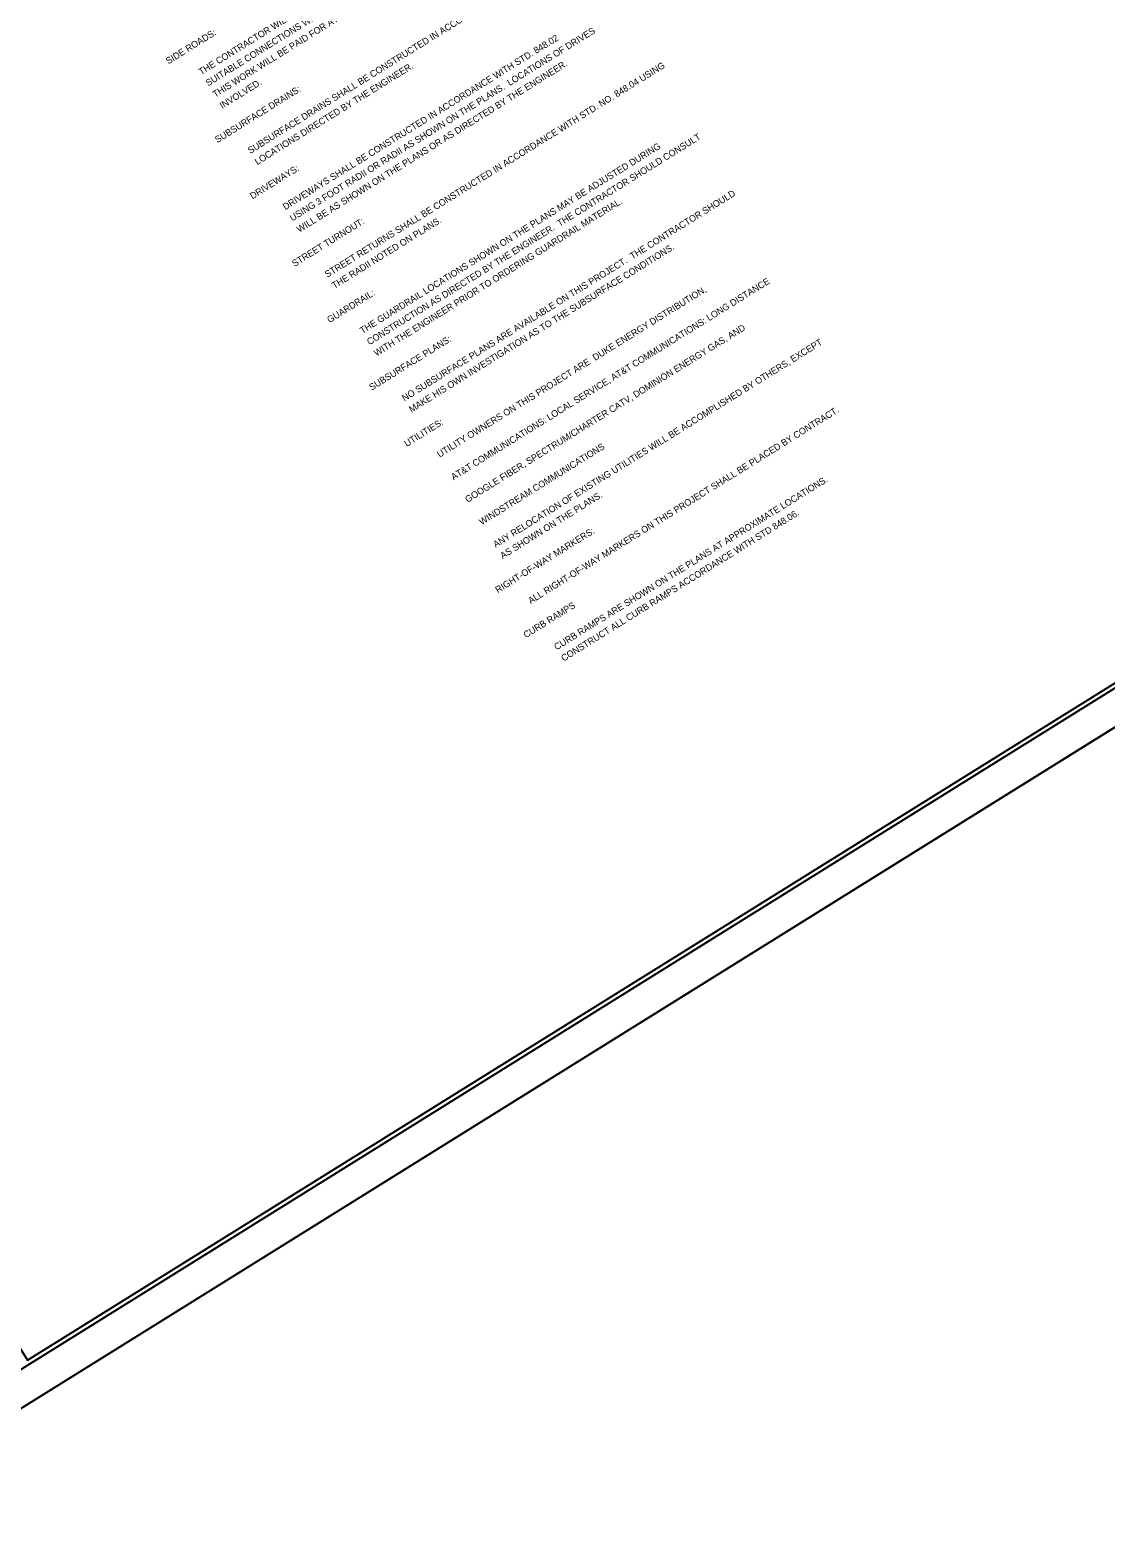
# Model space of a CAD drawing. Extents: x 2047559 to 2049567, y 759970 to 761789.
# Drawn here: x 2048269 to 2048918, y 759970 to 760880 of the extents above; entities that cross this region are included whole.
import ezdxf

# ---------------------------------------------------------------- set-up
doc = ezdxf.new("R2010")
doc.units = 0
for name, color, linetype in [('Sheet Cutting Line CELL', 7, 'Continuous'), ('Sheet Data Text CELL', 7, 'Continuous'), ('Sheet Plan CELL', 7, 'Continuous'), ('Sheet Plot Border Inside CELL', 7, 'Continuous'), ('Sheet Plot Border Outside CELL', 7, 'Continuous')]:
    doc.layers.add(name, color=color, linetype=linetype)

msp = doc.modelspace()

# ---------------------------------------------------------------- linework, layer by layer
at = {"layer": 'Sheet Cutting Line CELL'}
msp.add_line((2048137.94, 759969.81), (2049566.9, 760859.89), dxfattribs=at)
at = {"layer": 'Sheet Plan CELL'}
msp.add_lwpolyline([(2048985.43, 761761.24), (2047712.23, 760968.18), (2048267.37, 760076.94), (2049540.57, 760870)], close=True, dxfattribs=at)
at = {"layer": 'Sheet Plot Border Inside CELL'}
msp.add_lwpolyline([(2048138.4, 759993.66), (2049552.51, 760874.48), (2048994.72, 761769.97), (2047580.61, 760889.15)], close=True, dxfattribs=at)
at = {"layer": 'Sheet Plot Border Outside CELL'}
msp.add_lwpolyline([(2048137.94, 759969.81), (2049566.9, 760859.89), (2048987.97, 761789.33), (2047559, 760899.25)], close=True, dxfattribs=at)

# ---------------------------------------------------------------- texts
at = {"layer": 'Sheet Data Text CELL'}
for s, p in [('         SUITABLE CONNECTIONS WITH ALL ROADS, STREETS, AND DRIVES ENTERING THIS PROJECT.  ', (2048365.04, 760838.51)), ('         THE CONTRACTOR WILL BE REQUIRED TO DO ALL NECESSARY WORK TO PROVIDE ', (2048360.81, 760845.3)), ('         THIS WORK WILL BE PAID FOR AT THE CONTRACT UNIT PRICE FOR THE PARTICULAR ITEMS ', (2048369.27, 760831.72)), ('         SUBSURFACE DRAINS SHALL BE CONSTRUCTED IN ACCORDANCE WITH STD. NO. 815.02 AT ', (2048390.42, 760797.77)), ('SIDE ROADS:  ', (2048352.35, 760858.88)), ('         DRIVEWAYS SHALL BE CONSTRUCTED IN ACCORDANCE WITH STD. 848.02', (2048411.57, 760763.81)), ('         USING 3 FOOT RADII OR RADII AS SHOWN ON THE PLANS.  LOCATIONS OF DRIVES', (2048415.8, 760757.02)), ('         LOCATIONS DIRECTED BY THE ENGINEER.  ', (2048394.65, 760790.98)), ('         WILL BE AS SHOWN ON THE PLANS OR AS DIRECTED BY THE ENGINEER.  ', (2048420.03, 760750.23)), ('         STREET RETURNS SHALL BE CONSTRUCTED IN ACCORDANCE WITH STD. NO. 848.04 USING ', (2048436.94, 760723.07)), ('         INVOLVED.  ', (2048373.5, 760824.93)), ('SUBSURFACE DRAINS:', (2048381.96, 760811.35)), ('         CONSTRUCTION AS DIRECTED BY THE ENGINEER.  THE CONTRACTOR SHOULD CONSULT', (2048462.32, 760682.33)), ('         THE GUARDRAIL LOCATIONS SHOWN ON THE PLANS MAY BE ADJUSTED DURING ', (2048458.09, 760689.12)), ('DRIVEWAYS:  ', (2048403.11, 760777.39)), ('         WITH THE ENGINEER PRIOR TO ORDERING GUARDRAIL MATERIAL.', (2048466.55, 760675.54)), ('         NO SUBSURFACE PLANS ARE AVAILABLE ON THIS PROJECT.  THE CONTRACTOR SHOULD ', (2048483.47, 760648.38)), ('STREET TURNOUT:  ', (2048428.49, 760736.65)), ('         THE RADII NOTED ON PLANS.  ', (2048441.17, 760716.28)), ('         MAKE HIS OWN INVESTIGATION AS TO THE SUBSURFACE CONDITIONS.  ', (2048487.7, 760641.59)), ('GUARDRAIL:  ', (2048449.63, 760702.7)), ('         UTILITY OWNERS ON THIS PROJECT ARE  DUKE ENERGY DISTRIBUTION,', (2048504.62, 760614.42)), ('         AT&T COMMUNICATIONS: LOCAL SERVICE, AT&T COMMUNICATIONS: LONG DISTANCE', (2048513.08, 760600.84)), ('SUBSURFACE PLANS:  ', (2048475.01, 760661.96)), ('         GOOGLE FIBER, SPECTRUM/CHARTER CATV, DOMINION ENERGY GAS, AND', (2048521.54, 760587.26)), ('         ANY RELOCATION OF EXISTING UTILITIES WILL BE ACCOMPLISHED BY OTHERS, EXCEPT ', (2048538.46, 760560.1)), ('         ALL RIGHT-OF-WAY MARKERS ON THIS PROJECT SHALL BE PLACED BY CONTRACT.  ', (2048559.6, 760526.15)), ('UTILITIES:  ', (2048496.16, 760628.01)), ('         WINDSTREAM COMMUNICATIONS', (2048530, 760573.68)), ('        CURB RAMPS ARE SHOWN ON THE PLANS AT APPROXIMATE LOCATIONS.', (2048576.52, 760498.99)), ('         AS SHOWN ON THE PLANS.  ', (2048542.69, 760553.31)), ('        CONSTRUCT ALL CURB RAMPS ACCORDANCE WITH STD 848.06.', (2048580.75, 760492.2)), ('RIGHT-OF-WAY MARKERS:  ', (2048551.14, 760539.73)), ('CURB RAMPS', (2048568.06, 760512.57))]:
    msp.add_text(s, height=4, rotation=31.91803, dxfattribs=at).set_placement(p)

doc.saveas('drawing.dxf')
